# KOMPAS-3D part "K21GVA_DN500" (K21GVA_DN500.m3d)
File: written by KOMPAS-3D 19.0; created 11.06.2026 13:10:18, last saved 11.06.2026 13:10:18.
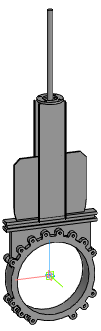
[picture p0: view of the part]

Document properties: Автор: Энергия; Полное имя файла: Z:\3.Личные\kachalov\001_3d для проектировщиков\2.5 Тип_K21GVA. Задвижка\_stp\_stp_K21GVA_DN50-DN1000_с фланцем\K21GVA_DN500.m3d

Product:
- Part/product: K21GVA_DN500

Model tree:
1. Операция без истории:1  (labels: K21GVA_DN500)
